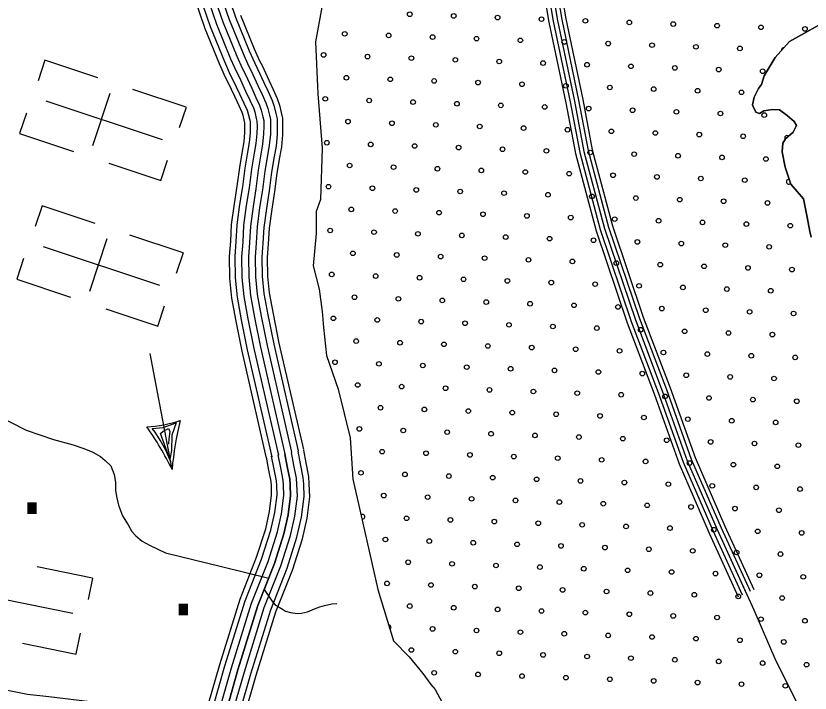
# Model space of a CAD drawing. Extents: x 1788175 to 1969470, y 584502 to 738744.
# Drawn here: x 1807019 to 1810667, y 711779 to 714890 of the extents above; entities that cross this region are included whole.
import ezdxf

# ---------------------------------------------------------------- set-up
doc = ezdxf.new("R2010")
doc.units = 0
for name, color, linetype in [('DESIGN - SCRATCH - User 1', 7, 'Continuous'), ('DESIGN - TRAFFIC CONTROL PERMANENT - Pavement Marking Text', 7, 'Continuous'), ('DESIGN - TRANSPORTATION - Edge of Traveled Way', 7, 'Continuous'), ('DESIGN - UTILITIES - Cable (Overhead) with Text', 7, 'Continuous'), ('DESIGN - UTILITIES - Cable (Underground) with Text', 7, 'Continuous'), ('SURVEY - CONTOURS - Index with Text', 7, 'Continuous'), ('SURVEY - DRAINAGE - Natural Features', 7, 'Continuous'), ('SURVEY - TRANSPORTATION - Roads', 7, 'Continuous')]:
    doc.layers.add(name, color=color, linetype=linetype)

msp = doc.modelspace()

# ---------------------------------------------------------------- linework, layer by layer
at = {"layer": 'DESIGN - SCRATCH - User 1'}
for points in [[(1808424.7, 714929.3), (1808394.8, 714771.1), (1808405.4, 714532.2), (1808425.7, 714282.3), (1808418.9, 714045.9), (1808398.7, 713991.8), (1808398.7, 713890.5), (1808385.2, 713741.9), (1808412.2, 713633.9), (1808425.7, 713532.5), (1808432.4, 713458.2), (1808445.9, 713329.9), (1808500, 713174.6), (1808554, 712951.7), (1808567.5, 712762.6), (1808601.3, 712607.2), (1808682.3, 712256), (1808752.8, 712019.6), (1808824.8, 711945.6), (1808888.8, 711869.6), (1808924.7, 711819.6), (1808944.7, 711795.6), (1808976.7, 711735.6)], [(1810671.6, 713873.3), (1810665.6, 713899.3), (1810653.6, 713965.4), (1810635.6, 714049.5), (1810577.6, 714117.5), (1810551.6, 714195.5), (1810537.6, 714265.6), (1810541.6, 714305.7), (1810553.6, 714325.7), (1810589.6, 714355.8), (1810603.6, 714385.9), (1810593.6, 714403.9), (1810561.6, 714431.9), (1810525.6, 714457.9), (1810493.6, 714459.8), (1810453.7, 714453.8), (1810433.7, 714441.7), (1810417.7, 714447.7), (1810405.7, 714473.7), (1810401.7, 714481.7), (1810409.7, 714515.8), (1810429.7, 714555.9), (1810443.6, 714573.9), (1810455.6, 714614), (1810505.6, 714698.2), (1810571.6, 714772.4), (1810703.5, 714844.7)]]:
    msp.add_lwpolyline(points, dxfattribs=at)
at = {"layer": 'DESIGN - TRAFFIC CONTROL PERMANENT - Pavement Marking Text'}
for centre in [(1808828.3, 714896.9), (1809030, 714889.4), (1809231.6, 714881.9), (1809433.2, 714874.5), (1809634.8, 714867), (1809836.4, 714859.5), (1810038, 714852.1), (1810239.6, 714844.6), (1810441.2, 714837.1), (1810642.8, 714829.7), (1808529.7, 714807.3), (1808731.3, 714799.8), (1808932.9, 714792.3), (1809134.5, 714784.9), (1809336.1, 714777.4), (1809537.7, 714769.9), (1809739.3, 714762.5), (1809940.9, 714755), (1810142.5, 714747.5), (1810344.2, 714740.1), (1808432.6, 714710.2), (1808634.2, 714702.7), (1808835.8, 714695.3), (1809037.4, 714687.8), (1809239, 714680.3), (1809440.6, 714672.9), (1809642.3, 714665.4), (1809843.9, 714657.9), (1810045.5, 714650.5), (1810247.1, 714643), (1808537.1, 714605.7), (1810448.7, 714635.5), (1808738.7, 714598.2), (1808940.3, 714590.7), (1809142, 714583.3), (1809343.6, 714575.8), (1809545.2, 714568.3), (1809746.8, 714560.9), (1809948.4, 714553.4), (1810150, 714545.9), (1810351.6, 714538.5), (1808440.1, 714508.6), (1808641.7, 714501.1), (1808843.3, 714493.7), (1809044.9, 714486.2), (1809246.5, 714478.7), (1809448.1, 714471.3), (1809649.7, 714463.8), (1809851.3, 714456.3), (1810052.9, 714448.9), (1810254.6, 714441.4), (1810456.2, 714433.9), (1808544.6, 714404.1), (1808746.2, 714396.6), (1808947.8, 714389.1), (1809149.4, 714381.7), (1809351, 714374.2), (1809552.6, 714366.7), (1809754.3, 714359.3), (1809955.9, 714351.8), (1810157.5, 714344.3), (1810359.1, 714336.9), (1808447.5, 714307), (1808649.1, 714299.5), (1808850.7, 714292.1), (1809052.4, 714284.6), (1809254, 714277.1), (1809455.6, 714269.7), (1809657.2, 714262.2), (1809858.8, 714254.7), (1810060.4, 714247.2), (1810262, 714239.8), (1810463.6, 714232.3), (1808552.1, 714202.4), (1808753.7, 714195), (1808955.3, 714187.5), (1809156.9, 714180), (1809358.5, 714172.6), (1809560.1, 714165.1), (1809761.7, 714157.6), (1809963.3, 714150.2), (1810164.9, 714142.7), (1810366.6, 714135.2), (1808455, 714105.4), (1808656.6, 714097.9), (1808858.2, 714090.4), (1809059.8, 714083), (1809261.4, 714075.5), (1809463, 714068), (1809664.7, 714060.6), (1809866.3, 714053.1), (1810067.9, 714045.6), (1810269.5, 714038.2), (1810471.1, 714030.7), (1808559.5, 714000.8), (1808761.1, 713993.4), (1808962.8, 713985.9), (1809164.4, 713978.4), (1809366, 713971), (1809567.6, 713963.5), (1809769.2, 713956), (1809970.8, 713948.6), (1810172.4, 713941.1), (1810374, 713933.6), (1810575.6, 713926.2), (1808462.5, 713903.8), (1808664.1, 713896.3), (1808865.7, 713888.8), (1809067.3, 713881.4), (1809268.9, 713873.9), (1809470.5, 713866.4), (1809672.1, 713859), (1809873.7, 713851.5), (1810075.3, 713844), (1810277, 713836.6), (1810478.6, 713829.1), (1808567, 713799.2), (1808768.6, 713791.8), (1808970.2, 713784.3), (1809171.8, 713776.8), (1809373.4, 713769.4), (1809575, 713761.9), (1809776.7, 713754.4), (1809978.3, 713747), (1810179.9, 713739.5), (1810381.5, 713732), (1808469.9, 713702.2), (1808671.5, 713694.7), (1810583.1, 713724.6), (1808873.1, 713687.2), (1809074.8, 713679.8), (1809276.4, 713672.3), (1809478, 713664.8), (1809679.6, 713657.4), (1809881.2, 713649.9), (1810082.8, 713642.4), (1810284.4, 713635), (1810486, 713627.5), (1808574.5, 713597.6), (1808776.1, 713590.1), (1808977.7, 713582.7), (1809179.3, 713575.2), (1809380.9, 713567.7), (1809582.5, 713560.3), (1809784.1, 713552.8), (1809985.7, 713545.3), (1810187.3, 713537.9), (1810389, 713530.4), (1810590.6, 713522.9), (1808477.4, 713500.5), (1808679, 713493.1), (1808880.6, 713485.6), (1809082.2, 713478.1), (1809283.8, 713470.7), (1809485.4, 713463.2), (1809687.1, 713455.7), (1809888.7, 713448.3), (1810090.3, 713440.8), (1810291.9, 713433.3), (1810493.5, 713425.9), (1808581.9, 713396), (1808783.5, 713388.5), (1808985.2, 713381.1), (1809186.8, 713373.6), (1809388.4, 713366.1), (1809590, 713358.7), (1809791.6, 713351.2), (1809993.2, 713343.7), (1810194.8, 713336.3), (1810396.4, 713328.8), (1808484.9, 713298.9), (1810598, 713321.3), (1808686.5, 713291.5), (1808888.1, 713284), (1809089.7, 713276.5), (1809291.3, 713269.1), (1809492.9, 713261.6), (1809694.5, 713254.1), (1809896.1, 713246.7), (1810097.7, 713239.2), (1810299.4, 713231.7), (1810501, 713224.3), (1808589.4, 713194.4), (1808791, 713186.9), (1808992.6, 713179.5), (1809194.2, 713172), (1809395.8, 713164.5), (1809597.4, 713157.1), (1809799.1, 713149.6), (1810000.7, 713142.1), (1810202.3, 713134.7), (1810403.9, 713127.2), (1810605.5, 713119.7), (1808693.9, 713089.9), (1808895.5, 713082.4), (1809097.2, 713074.9), (1809298.8, 713067.5), (1809500.4, 713060), (1809702, 713052.5), (1809903.6, 713045.1), (1810105.2, 713037.6), (1810306.8, 713030.1), (1810508.4, 713022.7), (1808596.9, 712992.8), (1808798.5, 712985.3), (1809000.1, 712977.9), (1809201.7, 712970.4), (1809403.3, 712962.9), (1809604.9, 712955.5), (1809806.5, 712948), (1810008.1, 712940.5), (1810209.7, 712933), (1810411.4, 712925.6), (1810613, 712918.1), (1808701.4, 712888.2), (1808903, 712880.8), (1809104.6, 712873.3), (1809306.2, 712865.8), (1809507.8, 712858.4), (1809709.5, 712850.9), (1809911.1, 712843.4), (1810112.7, 712836), (1810314.3, 712828.5), (1810515.9, 712821), (1808604.3, 712791.2), (1808805.9, 712783.7), (1809007.6, 712776.2), (1809209.2, 712768.8), (1809410.8, 712761.3), (1809612.4, 712753.8), (1809814, 712746.4), (1810015.6, 712738.9), (1810217.2, 712731.4), (1810418.8, 712724), (1810620.4, 712716.5), (1808708.9, 712686.6), (1808910.5, 712679.2), (1809112.1, 712671.7), (1809313.7, 712664.2), (1809515.3, 712656.8), (1809716.9, 712649.3), (1809918.5, 712641.8), (1810120.1, 712634.4), (1810321.8, 712626.9), (1810523.4, 712619.4), (1808813.4, 712582.1), (1809015, 712574.6), (1809216.6, 712567.2), (1809418.2, 712559.7), (1809619.9, 712552.2), (1809821.5, 712544.8), (1810023.1, 712537.3), (1810224.7, 712529.8), (1810426.3, 712522.4), (1810627.9, 712514.9), (1808716.3, 712485), (1808917.9, 712477.6), (1809119.6, 712470.1), (1809321.2, 712462.6), (1809522.8, 712455.2), (1809724.4, 712447.7), (1809926, 712440.2), (1810127.6, 712432.8), (1810329.2, 712425.3), (1810530.8, 712417.8), (1808820.9, 712380.5), (1809022.5, 712373), (1809224.1, 712365.6), (1809425.7, 712358.1), (1809627.3, 712350.6), (1809828.9, 712343.2), (1810030.5, 712335.7), (1810232.1, 712328.2), (1810433.8, 712320.8), (1810635.4, 712313.3), (1808723.8, 712283.4), (1808925.4, 712275.9), (1809127, 712268.5), (1809328.6, 712261), (1809530.2, 712253.5), (1809731.9, 712246.1), (1809933.5, 712238.6), (1810135.1, 712231.1), (1810336.7, 712223.7), (1810538.3, 712216.2), (1808828.3, 712178.9), (1809030, 712171.4), (1809231.6, 712163.9), (1809433.2, 712156.5), (1809634.8, 712149), (1809836.4, 712141.5), (1810038, 712134.1), (1810239.6, 712126.6), (1810441.2, 712119.1), (1810642.8, 712111.7), (1808932.9, 712074.3), (1809134.5, 712066.9), (1809336.1, 712059.4), (1809537.7, 712051.9), (1809739.3, 712044.5), (1809940.9, 712037), (1810142.5, 712029.5), (1810344.2, 712022.1), (1810545.8, 712014.6), (1808835.8, 711977.3), (1809037.4, 711969.8), (1809239, 711962.3), (1809440.6, 711954.9), (1809642.3, 711947.4), (1809843.9, 711939.9), (1810045.5, 711932.5), (1810247.1, 711925), (1810448.7, 711917.5), (1810650.3, 711910.1), (1808940.3, 711872.7), (1809142, 711865.3), (1809343.6, 711857.8), (1809545.2, 711850.3), (1809746.8, 711842.9), (1809948.4, 711835.4), (1810150, 711827.9), (1810351.6, 711820.5), (1810553.2, 711813)]:
    msp.add_circle(centre, 10.6, dxfattribs=at)
for centre, start, end in [((1810545.8, 714732.6), 91.1224, 185.6217), ((1810560.7, 714329.4), 49.4684, 215.61), ((1810568.2, 714127.8), 75.6691, 321.1678), ((1808611.8, 712589.6), 246.5853, 139.4033), ((1808731.3, 712081.8), 302.4513, 90.7558)]:
    msp.add_arc(centre, 10.6, start, end, dxfattribs=at)
at = {"layer": 'DESIGN - TRANSPORTATION - Edge of Traveled Way'}
for points in [[(1808424.7, 714929.3), (1808394.8, 714771.1), (1808405.4, 714532.2), (1808425.7, 714282.3), (1808418.9, 714045.9), (1808398.7, 713991.8), (1808398.7, 713890.5), (1808385.2, 713741.9), (1808412.2, 713633.9), (1808425.7, 713532.5), (1808432.4, 713458.2), (1808445.9, 713329.9), (1808500, 713174.6), (1808554, 712951.7), (1808567.5, 712762.6), (1808601.3, 712607.2), (1808682.3, 712256), (1808752.8, 712019.6), (1808824.8, 711945.6), (1808888.8, 711869.6), (1808924.7, 711819.6), (1808944.7, 711795.6), (1808976.7, 711735.6)], [(1810703.5, 714844.7), (1810571.6, 714772.4), (1810505.6, 714698.2), (1810455.6, 714614), (1810443.6, 714573.9), (1810429.7, 714555.9), (1810409.7, 714515.8), (1810401.7, 714481.7), (1810405.7, 714473.7), (1810417.7, 714447.7), (1810433.7, 714441.7), (1810453.7, 714453.8), (1810493.6, 714459.8), (1810525.6, 714457.9), (1810561.6, 714431.9), (1810593.6, 714403.9), (1810603.6, 714385.9), (1810589.6, 714355.8), (1810553.6, 714325.7), (1810541.6, 714305.7), (1810537.6, 714265.6), (1810551.6, 714195.5), (1810577.6, 714117.5), (1810635.6, 714049.5), (1810653.6, 713965.4), (1810665.6, 713899.3), (1810671.6, 713873.3)]]:
    msp.add_lwpolyline(points, dxfattribs=at)
at = {"layer": 'DESIGN - UTILITIES - Cable (Overhead) with Text'}
for p, q in [((1807736.7, 712806.5), (1807636.8, 713339.5)), ((1807696.3, 712999.5), (1807755.9, 713020.4)), ((1807755.9, 713020.4), (1807735.4, 712963.7)), ((1807644.5, 712994.1), (1807696.3, 712999.5)), ((1807658.3, 712978.4), (1807644.5, 712994.1)), ((1807682.5, 712940.9), (1807658.3, 712978.4)), ((1807683.3, 712971.3), (1807696.3, 712982.3)), ((1807696.3, 712982.3), (1807721, 712994.4)), ((1807721, 712994.4), (1807725.8, 712980.3)), ((1807725.8, 712980.3), (1807722.2, 712947.3)), ((1807707.3, 712894.9), (1807682.5, 712940.9)), ((1807727, 712853.3), (1807683.3, 712971.3)), ((1807722.2, 712947.3), (1807720.6, 712922.1)), ((1807735.4, 712963.7), (1807733.5, 712893.3)), ((1807730.3, 712841.1), (1807707.3, 712894.9)), ((1807733.5, 712893.3), (1807727, 712853.3))]:
    msp.add_line(p, q, dxfattribs=at)
for centre, radius, start, end in [((1807600.2, 713534.7), 532.3, 272.1903, 289.0487), ((1809118.5, 712693.8), 1386.4, 165.8987, 175.3373), ((1806346.5, 712116.1), 1552.3, 26.407, 34.8348)]:
    msp.add_arc(centre, radius, start, end, dxfattribs=at)
at = {"layer": 'DESIGN - UTILITIES - Cable (Underground) with Text'}
for p, q in [((1807152.9, 714685.9), (1807121.4, 714591.2)), ((1807396.4, 714604.6), (1807152.9, 714685.8)), ((1807801.1, 714469.8), (1807556.2, 714551.4)), ((1807451.2, 714533.6), (1807371, 714293)), ((1807068, 714443.6), (1807036.6, 714349.6)), ((1807801, 714469.6), (1807769.5, 714375.2)), ((1807036.5, 714349.1), (1807283.9, 714266.6)), ((1807684.7, 714133.2), (1807715.7, 714226.4)), ((1807446.1, 714212.5), (1807684.6, 714133)), ((1807139.4, 714017.2), (1807107.9, 713922.6)), ((1807382.9, 713935.9), (1807139.4, 714017.1)), ((1807437.7, 713865), (1807357.5, 713624.3)), ((1807787.6, 713801.1), (1807542.7, 713882.7)), ((1807787.5, 713800.9), (1807756, 713706.5)), ((1807054.5, 713774.9), (1807023.1, 713681)), ((1807023, 713680.4), (1807270.4, 713597.9)), ((1807432.6, 713543.9), (1807671.1, 713464.3)), ((1807671.2, 713464.5), (1807702.2, 713557.7)), ((1807370.8, 712307.4), (1807117.9, 712358.6)), ((1807370.8, 712307.2), (1807351.1, 712209.7)), ((1807296.4, 711959.1), (1807315.8, 712055.4)), ((1807049.9, 712008.8), (1807296.3, 711959))]:
    msp.add_line(p, q, dxfattribs=at)
for points in [[(1807157.6, 714499.4), (1807691.8, 714321.3)], [(1807144.1, 713830.7), (1807678.3, 713652.7)], [(1806728.6, 712258.4), (1807280.5, 712146.8)]]:
    msp.add_lwpolyline(points, dxfattribs=at)
at = {"layer": 'SURVEY - CONTOURS - Index with Text'}
for points in [[(1807948.9, 715020), (1807998.8, 714872.8), (1808062.7, 714717.1), (1808088, 714659.5), (1808099.8, 714636.6), (1808130.4, 714570.2), (1808149.9, 714528.4), (1808167.9, 714490.5), (1808175.7, 714465), (1808183.8, 714433.3), (1808188.4, 714413.3), (1808188.7, 714381.9), (1808188.1, 714346.9), (1808183.3, 714295.8), (1808175, 714248.6), (1808163.2, 714176), (1808151.8, 714090.9), (1808138.9, 714009.9), (1808126.9, 713920.5), (1808123, 713847.1), (1808118.1, 713781.8), (1808119.5, 713691.7), (1808127.8, 713610.2), (1808145.8, 713510.6), (1808173.1, 713375.3), (1808285.2, 712885.6)], [(1807978.3, 715029.9), (1808027.9, 714883.7), (1808091.2, 714729.3), (1808116, 714672.9), (1808127.7, 714650.2), (1808158.6, 714583.3), (1808178, 714541.6), (1808196.9, 714501.7), (1808205.6, 714473.3), (1808213.9, 714440.6), (1808219.3, 714417), (1808219.7, 714381.8), (1808219.1, 714345.2), (1808214.1, 714291.6), (1808205.5, 714243.4), (1808193.9, 714171.4), (1808182.5, 714086.4), (1808169.6, 714005.4), (1808157.8, 713917.6), (1808153.9, 713845.1), (1808149.1, 713780.9), (1808150.5, 713693.5), (1808158.5, 713614.5), (1808176.2, 713516.4), (1808203.4, 713381.8), (1808315.4, 712892.5)], [(1807836.5, 714981.8), (1807887.6, 714831.2), (1807953.4, 714670.7), (1807980.8, 714608.4), (1807993.1, 714584.5), (1808022.7, 714520.3), (1808042.5, 714477.9), (1808056.9, 714447.6), (1808061.3, 714433), (1808068.4, 714405.2), (1808069.8, 714399.2), (1808069.9, 714382.3), (1808069.5, 714353.3), (1808065.6, 714311.7), (1808057.9, 714268.4), (1808045.8, 714193.3), (1808034.3, 714108.1), (1808021.5, 714027.1), (1808008.7, 713931.7), (1808004.5, 713854.7), (1807999.3, 713785.3), (1808000.9, 713684.8), (1808010.2, 713593.6), (1808029.1, 713488.3), (1808057, 713350.3), (1808169.4, 712859.1)], [(1807860.8, 714990.1), (1807911.7, 714840.2), (1807977.1, 714680.8), (1808004, 714619.5), (1808016.2, 714595.8), (1808046.1, 714531.1), (1808065.8, 714488.8), (1808080.9, 714456.9), (1808086.1, 714439.9), (1808093.4, 714411.3), (1808095.5, 714402.3), (1808095.6, 714382.2), (1808095.2, 714351.9), (1808091.1, 714308.2), (1808083.3, 714264.1), (1808071.2, 714189.6), (1808059.8, 714104.4), (1808046.9, 714023.4), (1808034.3, 713929.3), (1808030.2, 713853.1), (1808025.1, 713784.6), (1808026.6, 713686.3), (1808035.7, 713597.2), (1808054.4, 713493.1), (1808082.1, 713355.7), (1808194.5, 712864.8)], [(1807890.2, 715000), (1807940.7, 714851.1), (1808005.6, 714692.9), (1808032, 714632.8), (1808044.1, 714609.4), (1808074.2, 714544.1), (1808093.8, 714502), (1808109.9, 714468.1), (1808116, 714448.3), (1808123.5, 714418.6), (1808126.4, 714406), (1808126.7, 714382.1), (1808126.2, 714350.2), (1808121.8, 714304.1), (1808113.8, 714258.9), (1808101.9, 714185), (1808090.5, 714099.9), (1808077.6, 714018.9), (1808065.2, 713926.4), (1808061.1, 713851.1), (1808056.1, 713783.7), (1808057.5, 713688.1), (1808066.4, 713601.6), (1808084.9, 713498.9), (1808112.4, 713362.2), (1808224.7, 712871.7)], [(1807919.6, 715010), (1807969.8, 714862), (1808034.1, 714705), (1808060, 714646.2), (1808072, 714623), (1808102.3, 714557.2), (1808121.9, 714515.2), (1808138.9, 714479.3), (1808145.8, 714456.6), (1808153.6, 714425.9), (1808157.4, 714409.6), (1808157.7, 714382), (1808157.1, 714348.6), (1808152.6, 714299.9), (1808144.4, 714253.8), (1808132.6, 714180.5), (1808121.1, 714095.4), (1808108.3, 714014.4), (1808096.1, 713923.4), (1808092, 713849.1), (1808087.1, 713782.8), (1808088.5, 713689.9), (1808097.1, 713605.9), (1808115.3, 713504.7), (1808142.8, 713368.8), (1808254.9, 712878.7)], [(1807919.6, 715010), (1807969.8, 714862), (1808034.1, 714705), (1808060, 714646.2), (1808072, 714623), (1808102.3, 714557.2), (1808121.9, 714515.2), (1808138.9, 714479.3), (1808145.8, 714456.6), (1808153.6, 714425.9), (1808157.4, 714409.6), (1808157.7, 714382), (1808157.1, 714348.6), (1808152.6, 714299.9), (1808144.4, 714253.8), (1808132.6, 714180.5), (1808121.1, 714095.4), (1808108.3, 714014.4), (1808096.1, 713923.4), (1808092, 713849.1), (1808087.1, 713782.8), (1808088.5, 713689.9), (1808097.1, 713605.9), (1808115.3, 713504.7), (1808142.8, 713368.8), (1808254.9, 712878.7)], [(1808051, 714892.4), (1808114, 714738.9), (1808138.3, 714683.5), (1808149.9, 714661), (1808181, 714593.7), (1808200.4, 714552.1), (1808220, 714510.6), (1808229.4, 714479.9), (1808237.9, 714446.4), (1808244, 714419.9), (1808244.4, 714381.7), (1808243.8, 714343.8), (1808238.6, 714288.3), (1808229.9, 714239.3), (1808218.4, 714167.8), (1808206.9, 714082.8), (1808194.1, 714001.8), (1808182.5, 713915.3), (1808178.6, 713843.5), (1808173.9, 713780.2), (1808175.2, 713695), (1808183, 713618), (1808200.5, 713521), (1808227.5, 713387), (1808339.5, 712898)], [(1807927.1, 711720.6), (1807979.4, 711904.1), (1808072.5, 712202.8), (1808148, 712394.8), (1808190.4, 712527.7), (1808209, 712608.7), (1808218.8, 712687.9), (1808217.2, 712732.9), (1808215.8, 712753.9), (1808204.9, 712808.6), (1808194, 712867.3)], [(1807957.3, 711713.5), (1808009.2, 711895.2), (1808101.8, 712192.5), (1808177.2, 712384.4), (1808220.3, 712519.5), (1808239.6, 712603.3), (1808249.9, 712686.6), (1808248.2, 712734.5), (1808246.6, 712758), (1808235.4, 712814.4), (1808224.5, 712873)], [(1808254.9, 712878.7), (1808265.8, 712820.3), (1808277.4, 712762.1), (1808279.2, 712736.1), (1808280.9, 712685.2), (1808270.1, 712597.9), (1808250.3, 712511.3), (1808206.5, 712374), (1808131, 712182.2), (1808038.9, 711886.3), (1807987.5, 711706.4)], [(1807987.5, 711706.4), (1808038.9, 711886.3), (1808131, 712182.2), (1808206.5, 712374), (1808250.3, 712511.3), (1808270.1, 712597.9), (1808280.9, 712685.2), (1808279.2, 712736.1), (1808277.4, 712762.1), (1808265.8, 712820.3), (1808254.9, 712878.7)], [(1808017.7, 711699.3), (1808068.6, 711877.5), (1808160.3, 712171.9), (1808235.7, 712363.6), (1808280.2, 712503.1), (1808300.7, 712592.6), (1808312, 712683.8), (1808310.1, 712737.7), (1808308.1, 712766.2), (1808296.2, 712826.1), (1808285.4, 712884.3)], [(1808048, 711692.2), (1808098.3, 711868.6), (1808189.6, 712161.6), (1808264.9, 712353.2), (1808310.1, 712495), (1808331.3, 712587.2), (1808343.1, 712682.4), (1808341.1, 712739.3), (1808338.9, 712770.3), (1808326.7, 712832), (1808315.9, 712890)], [(1808073, 711686.3), (1808122.9, 711861.2), (1808213.8, 712153.1), (1808289.2, 712344.6), (1808334.9, 712488.2), (1808356.6, 712582.7), (1808368.8, 712681.3), (1808366.8, 712740.6), (1808364.5, 712773.7), (1808351.9, 712836.9), (1808341.2, 712894.7)], [(1807903, 711726.2), (1807955.8, 711911.1), (1808049.2, 712211), (1808124.7, 712403.1), (1808166.5, 712534.2), (1808184.6, 712613), (1808194, 712689), (1808192.5, 712731.6), (1808191.2, 712750.6), (1808180.6, 712803.9), (1808169.7, 712862.8)]]:
    msp.add_lwpolyline(points, dxfattribs=at)
at = {"layer": 'SURVEY - DRAINAGE - Natural Features'}
for points in [[(1809326.3, 715770.4), (1809362.5, 715506), (1809408.6, 715203), (1809466.8, 714861.4), (1809544.9, 714490.7), (1809589.1, 714257.3), (1809683.8, 713902.3), (1809826.4, 713480), (1809950.5, 713153.4), (1810064.8, 712832.2), (1810203.4, 712514.4), (1810336.7, 712222.1)], [(1809346.1, 715773.1), (1809382.3, 715508.8), (1809428.4, 715206.1), (1809486.5, 714865.2), (1809564.5, 714494.6), (1809608.6, 714261.8), (1809702.9, 713908.1), (1809845.2, 713486.7), (1809969.3, 713160.3), (1810083.4, 712839.5), (1810221.7, 712522.5), (1810354.9, 712230.4)], [(1809366, 715775.8), (1809402.1, 715511.7), (1809448.1, 715209.3), (1809506.1, 714868.9), (1809584.1, 714498.5), (1809628.1, 714266.2), (1809722.1, 713913.9), (1809864.1, 713493.5), (1809988, 713167.2), (1810102, 712846.9), (1810240, 712530.7), (1810373.1, 712238.7)], [(1809385.8, 715778.5), (1809421.9, 715514.5), (1809467.9, 715212.5), (1809525.8, 714872.7), (1809603.7, 714502.4), (1809647.6, 714270.7), (1809741.3, 713919.6), (1809882.9, 713500.2), (1810006.8, 713174.1), (1810120.6, 712854.3), (1810258.2, 712538.8), (1810391.3, 712247)], [(1809404.6, 715781.1), (1809440.7, 715517.3), (1809486.6, 715215.5), (1809544.5, 714876.2), (1809622.4, 714506.1), (1809666.2, 714274.9), (1809759.5, 713925.1), (1809900.8, 713506.6), (1810024.6, 713180.7), (1810138.3, 712861.3), (1810275.6, 712546.5), (1810408.6, 712254.9)], [(1809448.1, 715209.3), (1809506.1, 714868.9), (1809584.1, 714498.5), (1809628.1, 714266.2), (1809722.1, 713913.9), (1809864.1, 713493.5), (1809988, 713167.2), (1810102, 712846.9), (1810240, 712530.7), (1810407.9, 712162.4), (1810509.9, 711928.2), (1810663.8, 711620)]]:
    msp.add_lwpolyline(points, dxfattribs=at)
at = {"layer": 'SURVEY - TRANSPORTATION - Roads'}
for points in [[(1806834, 713105.1), (1807066.1, 712987.4), (1807191.4, 712943.5), (1807283, 712920.1), (1807331.7, 712902.6), (1807372.4, 712886.7), (1807408, 712866.1), (1807429.7, 712847.8), (1807455.3, 712823.4), (1807470.7, 712783.1), (1807476.1, 712748.9), (1807477.2, 712711.6), (1807480.7, 712682), (1807490.4, 712642.5), (1807509.6, 712594.1), (1807535, 712551.7), (1807552.5, 712521.4), (1807570.1, 712501.1), (1807599.7, 712476.6), (1807633.4, 712458.1), (1807706.8, 712422.9), (1807963.7, 712361), (1808180.5, 712308)], [(1808159.6, 712254.8), (1808195.3, 712203.9), (1808208.8, 712187), (1808228.6, 712174.7), (1808244.4, 712164.5), (1808258.3, 712156.3), (1808280.2, 712149.9), (1808312.1, 712145.4), (1808330.8, 712146.4), (1808358.9, 712152.8), (1808390.4, 712166.3), (1808414.5, 712176), (1808436.6, 712181.7), (1808450.7, 712185.5), (1808470.1, 712189.8), (1808492.7, 712190.8)], [(1805226.6, 711452.6), (1805268.6, 711465.4), (1805319, 711492.7), (1805504.9, 711614.1), (1805676.5, 711715.8), (1805771.2, 711762.4), (1805856.1, 711802.5), (1805948.3, 711842), (1806020.8, 711874.9), (1806077.2, 711896.1), (1806135.4, 711915.3), (1806177.6, 711926.7), (1806234.4, 711938), (1806297.7, 711934.9), (1806395.3, 711915.5), (1806518.9, 711895.6), (1806686.9, 711851.1), (1806901.4, 711807.8), (1807072.8, 711775.2), (1807170.5, 711763.7), (1807980, 711665.6)]]:
    msp.add_lwpolyline(points, dxfattribs=at)

# ---------------------------------------------------------------- texts
at = {"layer": 'DESIGN - UTILITIES - Cable (Underground) with Text'}
for p in [(1807029.4, 712602.6), (1807725, 712136.5)]:
    msp.add_text('.', height=343, dxfattribs=at).set_placement(p)

doc.saveas('drawing.dxf')
